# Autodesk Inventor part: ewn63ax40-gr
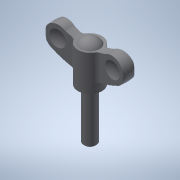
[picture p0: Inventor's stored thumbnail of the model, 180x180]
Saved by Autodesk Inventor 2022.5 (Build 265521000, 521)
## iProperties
Created: 2017-05
Part Number: ewn63ax40-gr
Material: 一般
Document SubType Name: Modeling
Designer: imaocorp
Density: 1 g/cm^3
Appearance: 既定
Author: imaocorp
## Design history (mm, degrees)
node "ewn63ax40-gr.x_t1"
node "ewn63ax40-gr"
node "Base1"
